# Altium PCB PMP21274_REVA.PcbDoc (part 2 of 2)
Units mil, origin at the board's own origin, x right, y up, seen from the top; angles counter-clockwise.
Board outline 3250 x 2700 mil, 4 copper layers (Top Layer, Signal Layer 1, Signal Layer 2, Bottom Layer), stack 61.6 mil thick; 81 components, 30 nets, 178 pads, 45 vias.
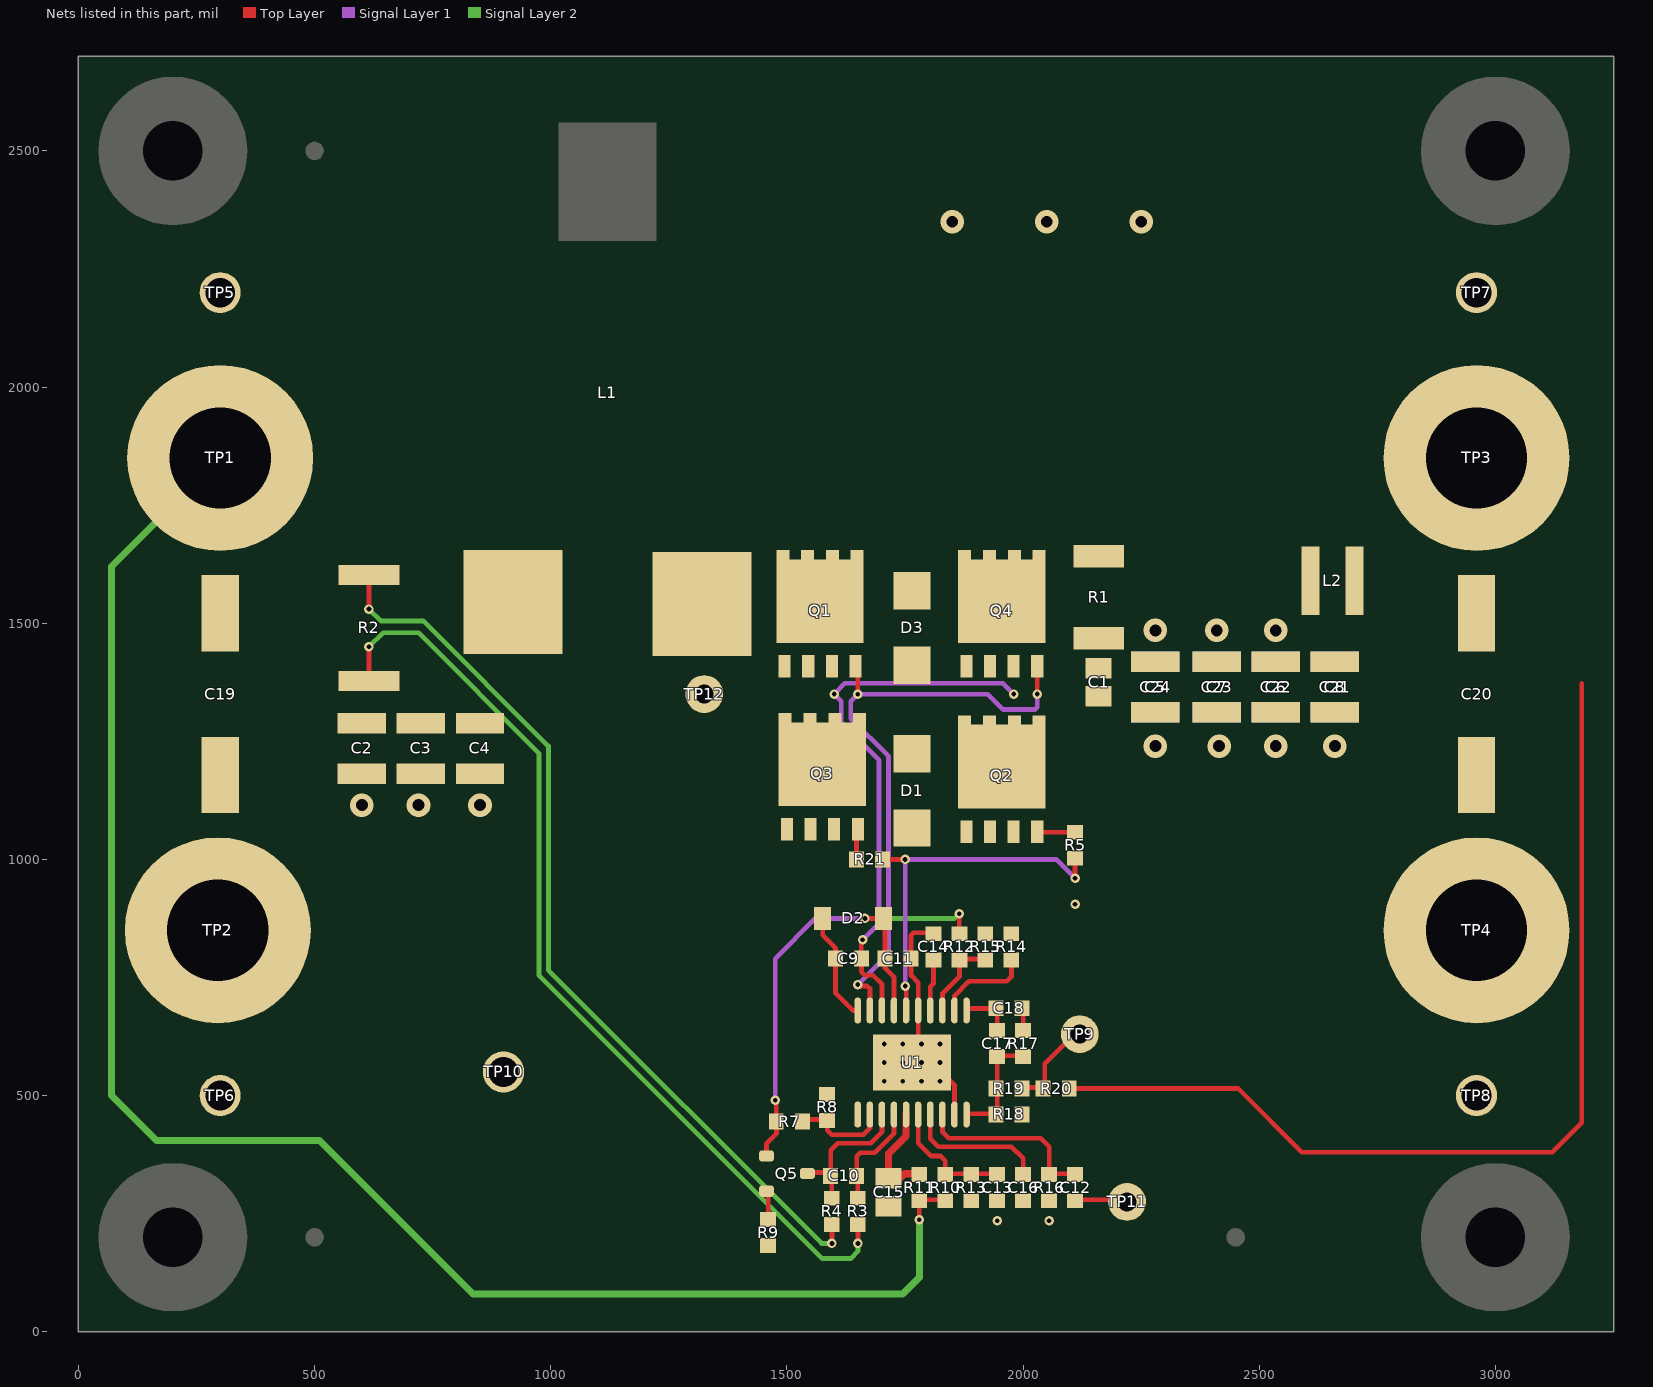
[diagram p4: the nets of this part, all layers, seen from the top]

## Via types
v1: diameter 20, hole 10, Top Layer to Bottom Layer, 32 vias
v2: diameter 50, hole 25, Top Layer to Bottom Layer, 13 vias

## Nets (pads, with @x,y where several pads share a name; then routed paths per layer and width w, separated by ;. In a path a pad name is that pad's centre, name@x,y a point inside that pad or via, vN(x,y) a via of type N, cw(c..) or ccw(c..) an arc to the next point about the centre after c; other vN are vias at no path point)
BST: C9.2 D2.1 U1.20 | length 233.3
  Top Layer w10: D2.1@1575.75,876.95 1575.75,839.42 1602.66,812.51 1602.66,717.34 1639.76,680.24 U1.20@1649.84,680.24
COMP: C17.1 C18.1 U1.11 | length 107.5
  Top Layer w10: U1.11@1882.58,684.39 1945.22,684.39 C17.1@1945.22,639.51
CSP_N: C10.1 Q5.3 R4.1 U1.3 | length 301.8
  Top Layer w10: Q5.3@1543.52,336.95 C10.1@1582.66,336.95 ; C10.1@1592.44,330 1592.44,384.17 1607.34,399.07 1677.34,399.07 1701.24,422.97 U1.3@1701.24,461.71 ; R4.1@1595,282.56 C10.1@1595,327.44
CSP_P: C10.2 R3.1 U1.4 | length 227.4
  Top Layer w10: C10.2@1647.56,330 1647.56,371.42 1655.22,379.07 1685.63,379.07 1726.83,420.28 U1.4@1726.83,461.71 ; R3.1@1650,282.56 C10.2@1650,327.56
CSPP_N: L1.1 R2.2 R4.2 | length 1929.3
  Top Layer w10: v1(615,1530) R2.2@615,1602.2 ; v1(1595.22,186.95) R4.2@1595.22,229.39
  Signal Layer 2 w10: v1(615,1530) 640,1505 730,1505 995,1240 995,765.28 1573.33,186.95 v1(1595.22,186.95)
EXT_SYNC: C12.2 TP11.1 | length 107.6
  Top Layer w10: C12.2@2110.22,279.39 TP11.1@2217.78,279.39
FB: C17.2 R17.1 R18.2 R19.1 U1.10 | length 242.4
  Top Layer w10: U1.10@1880.37,461.71 1945.47,461.71 1945.47,584.13 1999.96,584.13 R17.1@2000.22,584.39
GND: C2.2 C3.2 C4.2 C5.2 C6.2 C7.2 C8.2 C11.1 C13.2 C14.2 C15.2 C16.2 C19.2 C20.2 C21.2 C22.2 C23.2 C24.2 D1.2 Q2.1 Q2.2 Q2.3 Q3.1 Q3.2 Q3.3 R8.1 R9.1 R13.1 R14.1 R15.1 R16.1 R18.1 TP2.1 TP4.1 TP6.1 TP8.1 TP10.1 U1.9 U1.15 U1.21 | length 461.7
  Top Layer w10: U1.21@1778.01,584.74 1778.01,682.18 1778.01,739.15 1762.78,754.39 1762.78,791.95 1762.78,839.51 1767.78,844.51 C14.2@1810.22,844.51 ; U1.21@1784.9,571.95 1805.22,571.95 1854.78,522.38 U1.9@1854.78,461.71
  other v1: 1945,235 2055,235 1705.94,530.63 1745.31,530.63 1784.68,530.63 1824.06,530.63 1705.94,570 1745.31,570 1784.68,570 1824.06,570 1705.94,609.37 1745.31,609.37 1784.68,609.37 1824.06,609.37 2110,905
  other v2: 600,1115 720,1115 850,1115 2280,1240 2415,1240 2535,1240 2660,1240 1850,2350 2050,2350 2250,2350
LO: R5.2 R21.2 U1.16 | length 795.6
  Top Layer w10: R21.2@1702.56,1000 v1(1750,1000) ; v1(1750.22,731.95) 1752.42,729.74 U1.16@1752.42,682.18 ; R5.2@2100,991.83 R5.2@2100,1002.44 ; v1(2110,960) R5.2@2110,1002.44
  Signal Layer 1 w10: v1(1750,1000) 2070,1000 v1(2110,960) ; v1(1750.22,731.95) v1@1750.22,999.78
MODE: R12.1 R15.2 U1.13 | length 176.6
  Top Layer w10: U1.13@1829.19,682.18 1829.19,715.93 1865.22,751.95 R12.1@1865.22,788.9 ; R12.1@1865.22,789.39 R15.2@1920.22,789.39
NetC1_1: C1.1 R1.1
NetC5_1: C5.1 C6.1 C7.1 C8.1 C21.1 C22.1 C23.1 C24.1 D3.1 L2.1 Q1.5 Q1.6 Q1.7 Q1.8 Q1.9 Q4.5 Q4.6 Q4.7 Q4.8 Q4.9 R1.2
  other v2: 2280,1485 2410,1485 2535,1485
NetC18_2: C18.2 R17.2 | length 45
  Top Layer w10: R17.2@2000.22,639.51 C18.2@2000.22,684.51
NetQ2_4: Q2.4 R5.1 | length 88.8
  Top Layer w10: Q2.4@2021.22,1057.56 R5.1@2110,1057.56
NetQ3_4: Q3.4 R21.1 | length 61.2
  Top Layer w10: R21.1@1647.44,1000 Q3.4@1647.44,1061.22
NetQ5_2: Q5.2 R9.2 | length 56.7
  Top Layer w10: R9.2@1460.22,239.51 Q5.2@1460.22,296.24
NetR19_2: R19.2 R20.1 TP9.1 | length 196.6
  Top Layer w10: R19.2@2000.83,516.95 2045.71,516.95 2045.71,567.44 2110.22,631.95 TP9.1@2120.22,631.95
OPT: R7.1 R8.2 U1.2 | length 207.2
  Top Layer w10: R7.1@1532.78,446.95 1535.22,449.39 1585.22,449.39 1585.22,426.95 1595.22,416.95 1661.95,416.95 1675.65,430.65 U1.2@1675.65,461.71
RES: C14.1 U1.14 | length 99.9
  Top Layer w10: U1.14@1803.6,682.18 1803.6,730.33 1810.22,736.95 C14.1@1810.22,779.39
SLOPE: R14.2 U1.12 | length 194
  Top Layer w10: U1.12@1854.78,682.18 1854.78,711.52 1885.22,741.95 1965.22,741.95 1975.22,751.95 R14.2@1975.22,779.39
SS: C16.1 U1.7 | length 299.4
  Top Layer w10: U1.7@1803.6,461.71 1803.6,408.56 1820.22,391.95 1975.22,391.95 2000.22,366.95 C16.1@2000.22,334.51
SW_N: Q1.4 Q4.4 U1.19 | length 1291.3
  Top Layer w10: v1(1650,1349.7) Q1.4@1650,1408.78 ; v1@1653.05,731.95 1670.22,731.95 1675.65,726.52 U1.19@1675.65,682.18 ; v1(2030,1350) Q4.4@2030,1408.78
  Signal Layer 1 w10: v1(1650,735) 1715,800 1715,1218.28 1635,1298.28 1635,1334.7 v1(1650,1349.7) 1925.3,1349.7 1957.76,1317.24 2025,1317.24 2030,1322.24 v1(2030,1350)
SW_P: C1.2 C9.1 D1.1 D3.2 L1.2 Q1.1 Q1.2 Q1.3 Q2.5 Q2.6 Q2.7 Q2.8 Q2.9 Q3.5 Q3.6 Q3.7 Q3.8 Q3.9 Q4.1 Q4.2 Q4.3 TP12.1 U1.18 | length 1148.4
  Top Layer w10: v1@1657.56,827.56 C9.1@1657.56,790 C9.1@1657.78,789.78 ; C9.1@1657.78,791.95 C9.1@1657.78,789.78 ; U1.18@1701.24,682.18 1701.24,735.93 1682.17,755 1665,755 1657.78,762.22 C9.1@1657.78,789.78
  Signal Layer 1 w10: v1(1660,830) 1695,865 1695,1210 1615,1290 1615,1335 v1(1600,1350) 1622.76,1372.76 1957.24,1372.76 v1(1980,1350)
SYN/RT: C12.1 R16.2 U1.8 | length 390.1
  Top Layer w10: U1.8@1829.19,461.71 1829.19,422.97 1842.34,409.82 2037.34,409.82 2055.22,391.95 2055.22,334.51 C12.1@2110.22,334.51
SYNC: U1.1
UVLO: C13.1 R10.1 R13.2 U1.6 | length 272.6
  Top Layer w10: U1.6@1778.01,461.71 1778.01,399.15 1805.22,371.95 1825.22,371.95 1835.22,361.95 1835.22,334.51 C13.1@1945.22,334.51
V+: C2.1 C3.1 C4.1 C19.1 R2.1 R3.2 R10.2 R11.2 TP1.1 TP5.1 | length 5572.7
  Top Layer w10: R2.1@615,1377.8 v1(615,1450) ; v1(1650.22,186.95) R3.2@1650.22,229.39 ; v1(1780.22,236.95) 1780.22,279.39 R10.2@1835.22,279.39
  Signal Layer 2 w10: v1(615,1450) 645,1480 720,1480 975,1225 975,755 1575,155 1635,155 1650.22,170.22 v1(1650.22,186.95)
  Signal Layer 2 w15: TP1.1@300,1850 70,1620 70,500 165,405 510,405 835,80 1745,80 1780.22,115.22 v1(1780.22,236.95)
VCC: C11.2 D2.2 Q5.1 R7.2 R12.2 U1.17 | length 1134.7
  Top Layer w10: Q5.1@1456.91,374.35 1456.91,398.64 1477.66,419.39 R7.2@1477.66,446.95 ; R7.2@1477.44,445 v1@1477.44,487.56 ; v1(1665,875) D2.2@1704.47,875 ; D2.2@1707.66,873.98 1707.66,769.51 1726.83,750.33 U1.17@1726.83,682.18 ; R12.2@1865,842.56 v1(1865,885)
  Signal Layer 1 w10: v1(1475,490) 1475,790 1560,875 v1(1665,875)
  Signal Layer 2 w10: v1(1665,875) 1855,875 v1(1865,885)
VIN: C15.1 R11.1 U1.5 | length 219
  Top Layer w15: U1.5@1752.42,461.71 1752.42,414.15 1715.22,376.95 1715.22,326.48 1741.24,326.48 1749.27,334.51 R11.1@1780.22,334.51
VOUT: C20.1 L2.2 R20.2 TP3.1 TP7.1 | length 2096.7
  Top Layer w10: R20.2@2097.56,515 2455,515 2590,380 3120,380 3182.5,442.5 3182.5,1372.5
pads on no net: FID1.1 FID2.1 FID3.1 H1.1 H2.1 H3.1 H4.1 L1.3

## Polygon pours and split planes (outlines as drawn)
GND on Top Layer "GND" (solid, remove dead copper, pour order 10): 0,2700 0,0 3250,0 3250,2700
VOUT on Top Layer "Vout" (solid, remove dead copper, pour order 8): 2675,2300.09 2675,1470 2730,1470 2730,1350 3250,1350 3250,2305
NetC5_1 on Top Layer "C51" (solid, remove dead copper, pour order 6): 1450,1680 1450,1450 2070,1450 2070,1535 2215,1535 2214.88,1370 2710,1370 2710,1455 2650,1455 2650,1680
SW_P on Top Layer "SW" (solid, remove dead copper, pour order 4): 1200,1680 1200,1110 2070,1110 2070,1435 1425,1435 1425,1680
V+ on Top Layer "V+" (solid, remove dead copper, pour order 2): 0,2300 0,1375 530,1375 530,1245 915,1245 915,1400 715,1400 715,1465 520,1465 520,2300
GND on Signal Layer 1 "GND" (solid, remove dead copper, pour order 12): 0,2700 0,0 3250,0 3250,2700
GND on Signal Layer 2 "GND" (solid, remove dead copper, pour order 14): 0,2700 0,0 3250,0 3250,2700
GND on Bottom Layer "GND" (solid, remove dead copper, pour order 16): 0,2700 0,0 3250,0 3250,2700

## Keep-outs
Keep-Out Layer:
  text ".Layer_Name" at 577,-858.49 h60

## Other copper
Top Layer:
  rectangle net CSPP_N: 765,1435 835,1585
  rectangle net CSPP_N: 545,1585 1025,1680
  rectangle net NetC1_1: 2128.5,1385 2190,1485
  rectangle net SW_P: 2055,1318.9 2186.5,1365
  pour cut-out: 595,1470.32 595,1363.05 635,1363.05 635,1470.32
  text ".Layer_Name" at 577,-858.49 h60
Bottom Layer:
  rectangle net NetC5_1: 2225,1380 2720,1520
  text ".Layer_Name" at 577,-858.49 h60

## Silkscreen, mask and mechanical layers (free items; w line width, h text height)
Top Overlay:
  region: 1310,370 1010,370 1010,270 1310,270
  text "'.PRJ_Number'.PCB_Rev-" at 430,295 h108.27
  text ".Layer_Name" at 577,-858.49 h60
Bottom Overlay:
  text ".Layer_Name" at 577,-858.49 h60
Top Paste:
  text ".Layer_Name" at 577,-858.49 h60
Bottom Paste:
  text ".Layer_Name" at 577,-858.49 h60
Top Solder:
  text ".Layer_Name" at 577,-858.49 h60
  text ".Layer_Name" at 577,-858.49 h60
Bottom Solder:
  text ".Layer_Name" at 577,-858.49 h60
Drill Guide:
  text ".Layer_Name" at 577,-858.49 h60
M1 Board Outline:
  the board outline again, w10
  text ".Layer_Name" at 577,-858.49 h60
M2 Board Dimensions:
  rectangle: 0,-275 125,-150
  rectangle: 125,-400 500,-275
  lines w7: 0,-275 1000,-275 ; 125,-400 125,-150 ; 250,-400 250,-150 ; 500,-400 500,-150 ; 750,-400 750,-150 ; 0,-400 1000,-400 1000,-150 0,-150 0,-400
  text ".Layer_Name" at 577,-858.49 h60
M3 3D STEP Top:
  text ".Layer_Name" at 577,-858.49 h60
M4 3D STEP Bottom:
  text ".Layer_Name" at 577,-858.49 h60
M5 Assembly Top:
  lines w10: -292,-930.17 6308,-930.17 ; -292,-726.83 6310,-726.83 ; -292,-523.5 -292,-1133.5 3713,-1133.5 6310,-1133.5 6310,-523.5 -291.5,-523.5 -291.5,-1133.5 1284,-1133.5 ; 2173,-1133.5 2173,-523.5 ; 3440,-726.83 3440,-523.5 ; 4280,-726.83 4280,-523.5 ; 4902,-1140 4902,-937.17
  text "COMPONENTS MARKED 'DNP' SHOULD NOT BE POPULATED." at 1153.5,-318.5 h60
  text "ASSEMBLY VARIANT:" at 1153,-434 h60
  text ".VariantName" at 2189,-434 h60
  text "PCB VIEWED FROM TOP SIDE" at -228.5,-655.67 h60
  text "BOARD #:" at 2248,-655.67 h60
  text ".PRJ_Number" at 2793.5,-655.67 h60
  text "REV:" at 3638,-655.67 h60
  text ".PCB_Rev" at 3929.5,-655.67 h60
  text "SVN REV:" at 4476,-655.67 h60
  text ".VersionControl_RevNumber" at 4982,-655.67 h60
  text "TID #:" at 2248,-859 h60
  text ".TID" at 2793.5,-859 h60
  text "PLOT NAME =" at -228.5,-1064.34 h60
  text ".plot_File_Name" at 577,-1064.34 h60
  text "GENERATED    :" at 2250,-1064.34 h60
  text ".Print_Date" at 3119.5,-1064.34 h60
  text ".Print_Time" at 3848.5,-1064.34 h60
  text "TEXAS INSTRUMENTS" at 5113,-1064.34 h60
M6 Assembly Bottom:
  lines w10: -292.5,-727.33 6309.5,-727.33 ; -290.5,-930.67 6309.5,-930.67 ; 1115.5,-1140.5 1115.5,-937.67 ; 1737.5,-727.33 1737.5,-524 ; 2577.5,-727.33 2577.5,-524 ; 3844.5,-1134 3844.5,-524 ; 4733.5,-1134 6309,-1134 6309,-524 -292.5,-524 -292.5,-1134 2304.5,-1134 6309.5,-1134 6309.5,-524
  text "COMPONENTS MARKED 'DNP' SHOULD NOT BE POPULATED." at 6102,-318 h60
  text ".VariantName" at 5058,-434 h60
  text "ASSEMBLY VARIANT:" at 6097,-434 h60
  text ".VersionControl_RevNumber" at 1035.5,-656.17 h60
  text "SVN REV:" at 1541.5,-656.17 h60
  text ".PCB_Rev" at 2088,-656.17 h60
  text "REV:" at 2379.5,-656.17 h60
  text ".PRJ_Number" at 3224,-656.17 h60
  text "BOARD #:" at 3769.5,-656.17 h60
  text "PCB VIEWED FROM BOTTOM SIDE" at 6246,-656.17 h60
  text ".TID" at 3224,-859.5 h60
  text "TID #:" at 3769.5,-859.5 h60
  text "TEXAS INSTRUMENTS" at 904.5,-1064.84 h60
  text ".Print_Time" at 2169,-1064.84 h60
  text ".Print_Date" at 2898,-1064.84 h60
  text "GENERATED    :" at 3767.5,-1064.84 h60
  text ".plot_File_Name" at 5440.5,-1064.84 h60
  text "PLOT NAME =" at 6246,-1064.84 h60
M9 Title Sheet:
  drawing of 57 lines, arcs and shapes, not listed
  text "1" at 739.84,8036.5 h70
  text "2" at 3235.5,8036.5 h70
  text "3" at 5724.84,8036.5 h70
  text "4" at 8231.51,8036.5 h70
  text "5" at 10730.5,8036.5 h70
  text "6" at 13235.5,8036.5 h70
  text "A" at -416.5,6893.5 h70
  text "A" at 14383.5,6893.5 h70
  text "B" at -416.5,4513.5 h70
  text "B" at 14383.5,4513.5 h70
  text "C" at -416.5,2138.5 h70
  text "C" at 14383.5,2138.5 h70
  text "PROJECT TITLE:" at 11343.5,277.5 h45
  text ".PRJ_Title" at 11393.5,144.17 h70
  text "DESIGNED FOR:" at 11343.5,-23.5 h45
  text ".PRJ_Customer" at 11393.5,-163.5 h70
  text "D" at -416.5,-231.5 h70
  text "D" at 14383.5,-231.5 h70
  text "FILE NAME:" at 11343.5,-323.5 h45
  text ".PCB_File_Name_No_Path" at 11393.5,-443.5 h70
  text "Texas Instruments (TI) and/or its licensors do not warrant the accuracy or completeness of this specification" at 6374,-605.34 h45
  text "ENGINEER:" at 11343.5,-613.5 h45
  text "LAYOUT BY:" at 12848.5,-613.5 h45
  text "or any information contained therein. TI and/or its licensors do not warrant that this design will meet" at 6329.01,-718 h45
  text ".PRJ_Engineer" at 11393.5,-768.49 h70
  text ".PCB_Layout" at 12899,-768.49 h70
  text "the specifications, will be suitable for your application or fit for any particular purpose, or will operate in" at 6329.01,-830.67 h45
  text ".Layer_Name" at 577,-858.49 h60
  text "ALTIUM DESIGNER VERSION:" at 12848.5,-923.5 h45
  text "an implementation. TI and/or its licensors do not warrant that the design is production worthy. You should" at 6329.01,-943.33 h45
  text "completely validate and test your design implementation to confirm the system functionality for your application." at 6374,-1056 h45
  text ".print_Scale" at 11393.5,-1056.83 h70
  text ".Application_BuildNumber" at 12899,-1056.83 h70
  text "1" at 739.84,-1263.5 h70
  text "2" at 3235.5,-1263.5 h70
  text "3" at 5724.84,-1263.5 h70
  text "4" at 8231.51,-1263.5 h70
  text "5" at 10730.5,-1263.5 h70
  text "6" at 13235.5,-1263.5 h70
M10 Fab Notes:
  drawing of 189 lines, arcs and shapes, not listed
  text "DESIGN INFORMATION" at 12382.02,6356.17 h60
  text "MIN. TRACK WIDTH:" at 11737.46,6224.05 h60
  text "10" at 12833.7,6224.05 h60
  text "MIL" at 12988.46,6224.05 h60
  text "MIN. CLEARANCE:" at 11737.46,6099.92 h60
  text "0.2" at 12773.7,6099.93 h60
  text "mm" at 12988.46,6099.92 h60
  text "MIN. VIA PAD SIZE:" at 11737.46,5975.8 h60
  text "20" at 12803.71,5975.8 h60
  text "MIL" at 12988.46,5975.8 h60
  text "0.05mm (2MIL)" at 12432.46,5845.9 h60
  text "MINIMUM ANNULAR RING" at 11408.23,5837.67 h60
  text "EXTERNAL" at 13140.46,5837.67 h60
  text "PER" at 11608.23,5727.55 h60
  text "IPC-D-275 CLASS 2 LEVEL C" at 11828.23,5727.54 h60
  text "MIL, HOLES" at 13316.46,5627.07 h60
  text "+/-" at 12924,5618.48 h60
  text "+/-" at 13778,5618.48 h60
  text "REGISTRATION TOLERANCES:" at 11408.23,5617.42 h60
  text "METAL" at 12608,5617.42 h60
  text "5" at 13184.2,5617.42 h60
  text "3" at 14017.2,5617.42 h60
  text "MIL" at 14133.46,5617.42 h60
  text "HOLE SIZE TOLERANCE (UNLESS OTHERWISE SPECIFIED):" at 11408.23,5519.1 h60
  text "+/-" at 13778,5516.23 h60
  text "3" at 14017.2,5515.17 h60
  text "MIL" at 14133.46,5515.17 h60
  text "MATERIAL:" at 11333.46,5377.52 h60
  text "FR-4 High Tg" at 12319.9,5249 h60
  text "X" at 12175.46,5241.01 h60
  text "FR-408" at 11754.46,5236.49 h60
  text "OTHER" at 13242.46,5236.49 h60
  text "62 MIL (1.6mm) +/-10%" at 12074.56,5093.46 h60
  text "X" at 11954.46,5091.01 h60
  text "THICKNESS:" at 11408.23,5085.24 h60
  text "OTHER" at 13359.46,5085.24 h60
  text "TOLERANCE:" at 11408.23,4946.92 h60
  text "X" at 12256.46,4946.92 h60
  text "ANSI IPC-6012 TYPE 3 CLASS 2" at 12434.48,4946.92 h60
  text "OTHER +/-" at 12434.46,4802.73 h60
  text "BOW & TWIST:" at 11408.23,4657.54 h60
  text "X" at 12256.46,4657.54 h60
  text "ANSI IPC-6012 TYPE 3 CLASS 2" at 12434.48,4657.54 h60
  text "OTHER +/-" at 12434.46,4510.85 h60
  text "DRILLING:" at 11333.46,4380.23 h60
  text "NC_DRILL FILES" at 13094.46,4275.04 h60
  text "REFERENCE:" at 11408.23,4271.1 h60
  text "X" at 12065.46,4271.01 h60
  text "AS SHOWN" at 12243.46,4271.1 h60
  text "X" at 12966.46,4271.1 h60
  text "OTHER" at 13392.46,4128.85 h60
  text "PTH COPPER THICKNESS:" at 11407.91,4125.32 h60
  text "X" at 12547.14,4125.32 h60
  text "20-30 um" at 12675.14,4125.32 h60
  text "BOARD FINISH:" at 11333.46,3977.73 h60
  text "SILKSCREEN:" at 11488.68,3867.6 h60
  text "X" at 12446.46,3867.6 h60
  text "TOP" at 12563.46,3867.6 h60
  text "X" at 12956.46,3867.6 h60
  text "BOTTOM" at 13074.46,3867.6 h60
  text "SILKSCREEN COLOR:" at 11488.68,3712.41 h60
  text "X" at 12445.46,3712.41 h60
  text "WHITE" at 12563.46,3712.41 h60
  text "OTHER" at 13074.46,3712.41 h60
  text "X" at 12576.46,3568.96 h60
  text "GREEN" at 12694.46,3568.96 h60
  text "OTHER" at 13312.46,3568.96 h60
  text "SOLDER RESIST COLOR:" at 11488.68,3562.1 h60
  text "X" at 12576.46,3414.71 h60
  text "MATTE" at 12694.46,3414.71 h60
  text "SEMI-GLOSS" at 13312,3414.07 h60
  text "IMMERSION GOLD (ENIG)" at 12394.46,3241.94 h60
  text "ENEPIG" at 13732,3234.72 h60
  text "SURFACE FINISH:" at 11333.46,3233.72 h60
  text "X" at 12216.46,3233.72 h60
  text "IMM. TIN/SILVER OR EQUIV" at 11663,3096.4 h60
  text "OTHER" at 13094.46,3092.47 h60
  text "ARRAY/PANEL:" at 11333.46,2937.09 h60
  text "X" at 12215,2930 h60
  text "CUT AND TRIM PER M1 BOARD OUTLINE" at 12394.46,2928.87 h60
  text "N.C. ROUTE" at 12394.46,2792.9 h60
  text "V. SCORE" at 13260.46,2792.9 h60
  text "CERTIFICATION:" at 11333.46,2663.77 h60
  text "MATERIALS AND WORKMANSHIP FOR ALL PCBS" at 12058.46,2663.77 h60
  text "TO MEET OR EXCEED THE REQUIREMENTS OF:" at 12058.46,2569.71 h60
  text "X" at 11695.97,2441.08 h60
  text "ANSI IPC-A-600F CLASS ->" at 11823.96,2441.08 h60
  text "X" at 13471.97,2441.08 h60
  text "2" at 13581.96,2441.08 h60
  text "1" at 13266.96,2439.58 h60
  text "3" at 13935.96,2439.58 h60
  text "X" at 12507.97,2293.39 h60
  text "RoHS" at 12635.96,2293.39 h60
  text "OTHER" at 13280.36,2293.39 h60
  text "PER ORDER" at 13677.42,2293.39 h60
  text "ALL BOARDS MUST MEET OR EXCEED UL94-V0 REQUIREMENTS." at 11361,2139.57 h60
  text "PCB MUST BEAR THE UL94V-0 UL REGISTERED MATERIAL ID NUMBER" at 11361,2023.5 h60
  text "ADDITIONAL REQUIREMENTS:" at 11333.46,1854.08 h60
  text "MICROSECTION:" at 11408.23,1746.95 h60
  text "YES" at 12313.96,1746.95 h60
  text "REQUIRED" at 13175.46,1602.62 h60
  text "BARE BOARD ELEC. TEST:" at 11408.23,1599.76 h60
  text "NONE" at 12713.96,1599.76 h60
  text "X" at 13057.46,1599.76 h60
  text "PER ORDER" at 13767.46,1599.76 h60
  text "XX MIL VIAS REQUIRE NON-CONDUCTIVE FILL AND PLANARIZE" at 11576.38,1394.82 h59
  text "XX MIL VIAS REQUIRE CONDUCTIVE FILL AND PLANARIZE" at 11584.38,1290.84 h60
  text "OUTER XX MIL VIAS REQUIRE 50 OHM SINGLE-ENDED IMPEDANCE" at 11583.39,1127.46 h58
  text "LAYER 2 & 3 (INNER LAYERS) XX MIL WIDE, XX MIL SPACE / TRACES REQUIRE 100 OHM DIFFERENTIAL IMPEDANCE" at 11575.39,891.74 h60
  text ".Layer_Name" at 577,-858.49 h60
M11 Gerber Information:
  lines w10: -292,-930.17 6308,-930.17 ; -292,-726.83 6310,-726.83 ; -292,-523.5 -292,-1133.5 3713,-1133.5 6310,-1133.5 6310,-523.5 -291.5,-523.5 -291.5,-1133.5 1284,-1133.5 ; 2173,-1133.5 2173,-523.5 ; 3440,-726.83 3440,-523.5 ; 4280,-726.83 4280,-523.5 ; 4902,-1140 4902,-937.17
  text "ALL ARTWORK VIEWED FROM TOP SIDE" at -228.5,-655.67 h60
  text "BOARD #:" at 2248,-655.67 h60
  text ".PRJ_Number" at 2793.5,-655.67 h60
  text "REV:" at 3638,-655.67 h60
  text ".PCB_Rev" at 3929.5,-655.67 h60
  text "SVN REV:" at 4476,-655.67 h60
  text ".VersionControl_RevNumber" at 4982,-655.67 h60
  text "LAYER NAME =" at -228.5,-858.49 h60
  text "TID #:" at 2248,-859 h60
  text ".TID" at 2793.5,-859 h60
  text "PLOT NAME =" at -228.5,-1064.34 h60
  text ".plot_File_Name" at 577,-1064.34 h60
  text "GENERATED    :" at 2250,-1064.34 h60
  text ".Print_Date" at 3119.5,-1064.34 h60
  text ".Print_Time" at 3848.5,-1064.34 h60
  text "TEXAS INSTRUMENTS" at 5113,-1064.34 h60
M12 Stackup:
  drawing of 437 lines, arcs and shapes, not listed
  text "Layer" at 4742.5,5636.5 h60
  text "Name" at 5152.41,5636.5 h60
  text "Material" at 6092.15,5636.5 h60
  text "Thickness" at 6951.92,5636.5 h60
  text "Constant" at 7601.76,5636.5 h60
  text "Board Layer Stack" at 8171.62,5636.5 h60
  text "1" at 4742.5,5516.5 h60
  text "Top Overlay" at 5152.41,5516.5 h60
  text "2" at 4742.5,5396.5 h60
  text "Top Solder" at 5152.41,5396.5 h60
  text "Solder Resist" at 6092.15,5396.5 h60
  text "0.40mil" at 6951.92,5396.5 h60
  text "3.5" at 7601.76,5396.5 h60
  text "3" at 4742.5,5276.5 h60
  text "Top Layer" at 5152.41,5276.5 h60
  text "Copper" at 6092.15,5276.5 h60
  text "1.40mil" at 6951.92,5276.5 h60
  text "4" at 4742.5,5156.5 h60
  text "Dielectric1" at 5152.41,5156.5 h60
  text "FR-4" at 6092.15,5156.5 h60
  text "14.00mil" at 6951.92,5156.5 h60
  text "4.2" at 7601.76,5156.5 h60
  text "5" at 4742.5,5036.5 h60
  text "Signal Layer 1" at 5152.41,5036.5 h60
  text "Copper" at 6092.15,5036.5 h60
  text "1.40mil" at 6951.92,5036.5 h60
  text "6" at 4742.5,4916.5 h60
  text "Dielectric 2" at 5152.41,4916.5 h60
  text "28.00mil" at 6951.92,4916.5 h60
  text "4.2" at 7601.76,4916.5 h60
  text "7" at 4742.5,4796.5 h60
  text "Signal Layer 2" at 5152.41,4796.5 h60
  text "Copper" at 6092.15,4796.5 h60
  text "1.40mil" at 6951.92,4796.5 h60
  text "8" at 4742.5,4676.5 h60
  text "Dielectric 3" at 5152.41,4676.5 h60
  text "14.00mil" at 6951.92,4676.5 h60
  text "4.2" at 7601.76,4676.5 h60
  text "9" at 4742.5,4556.5 h60
  text "Bottom Layer" at 5152.41,4556.5 h60
  text "Copper" at 6092.15,4556.5 h60
  text "1.40mil" at 6951.92,4556.5 h60
  text "10" at 4742.5,4436.5 h60
  text "Bottom Solder" at 5152.41,4436.5 h60
  text "Solder Resist" at 6092.15,4436.5 h60
  text "0.40mil" at 6951.92,4436.5 h60
  text "3.5" at 7601.76,4436.5 h60
  text "11" at 4742.5,4316.5 h60
  text "Bottom Overlay" at 5152.41,4316.5 h60
  text ".Layer_Name" at 577,-858.49 h60
M13 Component Bodies Top:
  text ".Layer_Name" at 577,-858.49 h60
M14 Component Bodies Bottom:
  text ".Layer_Name" at 577,-858.49 h60
M15 Courtyards Top:
  text ".Layer_Name" at 577,-858.49 h60
M16 Courtyards Bottom:
  text ".Layer_Name" at 577,-858.49 h60
Drill Drawing:
  circle w10: c5363.72,2769 r27.63
  lines w10: 5336.09,2672.31 5391.34,2672.31 5363.72,2617.06 5336.09,2672.31 ; 5336.09,2865.7 5391.34,2865.7 5391.34,2920.95 5336.09,2920.95 5336.09,2865.7 ; 5336.09,3003.83 5349.9,3003.83 5363.72,2990.02 5377.53,3003.83 5391.34,3003.83 5377.53,3017.64 5391.34,3031.46 5377.53,3031.46 5363.72,3045.27 5349.9,3031.46 5336.09,3031.46 5349.9,3017.64 5336.09,3003.83 ; 5336.09,3114.34 5363.72,3128.15 5391.34,3114.34 5377.53,3141.96 5391.34,3169.59 5363.72,3155.78 5336.09,3169.59 5349.9,3141.96 5336.09,3114.34 ; 5336.09,3252.47 5349.9,3252.47 5349.9,3238.66 5377.53,3238.66 5377.53,3252.47 5391.34,3252.47 5391.34,3280.1 5377.53,3280.1 5377.53,3293.91 5349.9,3293.91 5349.9,3280.1 5336.09,3280.1 5336.09,3252.47
  lines w12: 5286,2579.76 8517.49,2579.76 ; 5286,3325.68 8517.49,3325.68 ; 5623.86,2455.44 5623.86,3450 ; 5955.86,2455.44 5955.86,3450 ; 6592.43,2455.44 6592.43,3450 ; 6851.57,2455.44 6851.57,3450 ; 7226.72,2455.44 7226.72,3450 ; 7951.05,2455.44 7951.05,3450 ; 5286,2455.44 8517.49,2455.44 8517.49,3450 5286,3450 5286,2455.44
  text "Symbol" at 5360.59,3362.98 h72
  text "Quantity" at 5661.16,3362.98 h72
  text "Finished Hole Size" at 5993.16,3362.98 h72
  text "Plated" at 6629.72,3362.98 h72
  text "Hole Type" at 6888.86,3362.98 h72
  text "Drill Layer Pair" at 7264.02,3362.98 h72
  text "Hole Tolerance" at 7988.35,3362.98 h72
  text "32" at 5661.16,3238.66 h60
  text "10.00mil (0.254mm)" at 5993.16,3238.66 h60
  text "PTH" at 6629.72,3238.66 h60
  text "Round" at 6888.86,3238.66 h60
  text "Top Layer - Bottom Layer" at 7264.02,3238.66 h60
  text "13" at 5661.16,3114.34 h60
  text "25.00mil (0.635mm)" at 5993.16,3114.34 h60
  text "PTH" at 6629.72,3114.34 h60
  text "Round" at 6888.86,3114.34 h60
  text "Top Layer - Bottom Layer" at 7264.02,3114.34 h60
  text "3" at 5661.16,2990.02 h60
  text "40.00mil (1.016mm)" at 5993.16,2990.02 h60
  text "PTH" at 6629.72,2990.02 h60
  text "Round" at 6888.86,2990.02 h60
  text "Top Layer - Bottom Layer" at 7264.02,2990.02 h60
  text "5" at 5661.16,2865.7 h60
  text "63.00mil (1.600mm)" at 5993.16,2865.7 h60
  text "PTH" at 6629.72,2865.7 h60
  text "Round" at 6888.86,2865.7 h60
  text "Top Layer - Bottom Layer" at 7264.02,2865.7 h60
  text "4" at 5661.16,2741.38 h60
  text "125.98mil (3.200mm)" at 5993.16,2741.38 h60
  text "PTH" at 6629.72,2741.38 h60
  text "Round" at 6888.86,2741.38 h60
  text "Top Layer - Bottom Layer" at 7264.02,2741.38 h60
  text "4" at 5661.16,2617.06 h60
  text "214.57mil (5.450mm)" at 5993.16,2617.06 h60
  text "PTH" at 6629.72,2617.06 h60
  text "Round" at 6888.86,2617.06 h60
  text "Top Layer - Bottom Layer" at 7264.02,2617.06 h60
  text "61 Total" at 5661.16,2492.74 h60
  text ".Layer_Name" at 577,-858.49 h60
M17 Embedded Cavity:
  text ".Layer_Name" at 577,-858.49 h60
M18 Embedded Assembly:
  text ".Layer_Name" at 577,-858.49 h60
M19 Embedded Keepout:
  text ".Layer_Name" at 577,-858.49 h60

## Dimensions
0,-400 to 1000,-400 on M2 Board Dimensions
0,0 to 0,2700 on M2 Board Dimensions
0,0 to 3250,0 on M2 Board Dimensions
